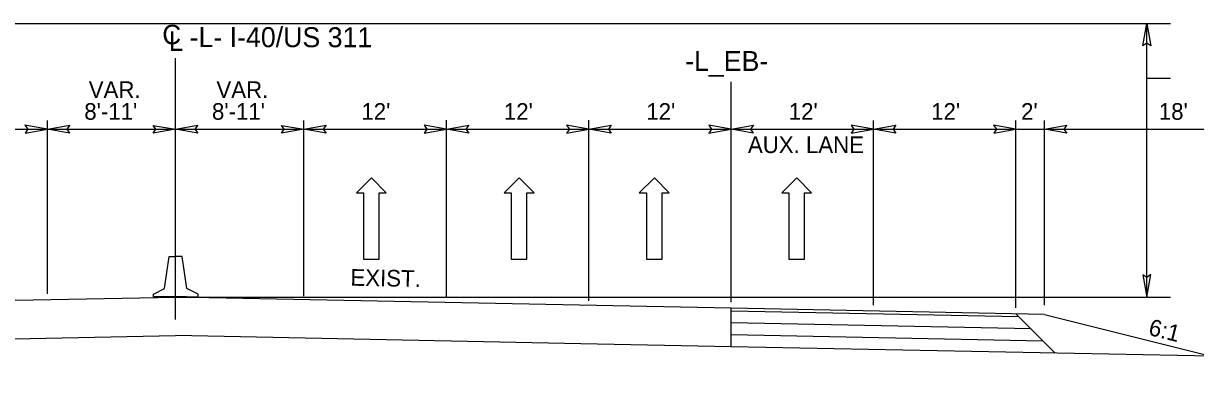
# Model space of a CAD drawing. Extents: x 1726582 to 1728895, y 538986 to 541550.
# Drawn here: x 1727397 to 1727891.1, y 541295.4 to 541445 of the extents above; entities that cross this region are included whole.
import ezdxf

# ---------------------------------------------------------------- set-up
doc = ezdxf.new("R2010")
doc.units = 0
for name, color, linetype in [('Default', 7, 'Continuous'), ('GSProposed', 7, 'Continuous'), ('GSRelocate', 7, 'Continuous'), ('GSRemove', 7, 'Continuous'), ('GSReplace', 7, 'Continuous')]:
    doc.layers.add(name, color=color, linetype=linetype)

msp = doc.modelspace()

# ---------------------------------------------------------------- linework, layer by layer
at = {"layer": 'Default'}
for p, q in [((1727250.93, 541445), (1727880.5, 541445)), ((1727870.5, 541329.79), (1727870.5, 541445)), ((1727695.28, 541327.57), (1727695.28, 541420.48)), ((1727870.5, 541422.01), (1727880.5, 541422.01)), ((1727407.04, 541331.18), (1727407.04, 541404.16)), ((1727515.13, 541330.19), (1727515.13, 541404.16)), ((1727575.29, 541329.97), (1727575.29, 541404.31)), ((1727635.34, 541328.19), (1727635.34, 541404.28)), ((1727695.28, 541327.57), (1727695.28, 541404.28)), ((1727755.32, 541326.37), (1727755.32, 541404.16)), ((1727815.37, 541326.37), (1727815.37, 541404.16)), ((1727815.37, 541325.17), (1727815.37, 541404.16)), ((1727827.38, 541326.37), (1727827.38, 541404.16)), ((1727346.99, 541400.46), (1727407.04, 541400.46)), ((1727407.04, 541400.46), (1727461.04, 541400.46)), ((1727461.04, 541400.46), (1727515.24, 541400.46)), ((1727515.24, 541400.46), (1727575.29, 541400.46)), ((1727575.29, 541400.46), (1727635.34, 541400.46)), ((1727635.34, 541400.46), (1727695.38, 541400.46)), ((1727695.38, 541400.46), (1727755.43, 541400.46)), ((1727755.43, 541400.46), (1727815.48, 541400.46)), ((1727755.43, 541400.46), (1727815.48, 541400.46)), ((1727815.48, 541400.46), (1727827.38, 541400.46)), ((1727827.38, 541400.46), (1727935.46, 541400.46)), ((1727543.74, 541379.98), (1727537.34, 541373.68)), ((1727549.94, 541373.68), (1727543.74, 541379.98)), ((1727606, 541379.98), (1727599.6, 541373.68)), ((1727612.2, 541373.68), (1727606, 541379.98)), ((1727663, 541379.98), (1727656.6, 541373.68)), ((1727669.2, 541373.68), (1727663, 541379.98)), ((1727723.05, 541379.98), (1727716.65, 541373.68)), ((1727729.25, 541373.68), (1727723.05, 541379.98)), ((1727537.34, 541373.68), (1727540.34, 541373.68)), ((1727540.34, 541373.68), (1727540.34, 541345.68)), ((1727546.94, 541345.68), (1727546.94, 541373.68)), ((1727546.94, 541373.68), (1727549.94, 541373.68)), ((1727599.6, 541373.68), (1727602.6, 541373.68)), ((1727602.6, 541373.68), (1727602.6, 541345.68)), ((1727609.2, 541345.68), (1727609.2, 541373.68)), ((1727609.2, 541373.68), (1727612.2, 541373.68)), ((1727656.6, 541373.68), (1727659.6, 541373.68)), ((1727659.6, 541373.68), (1727659.6, 541345.68)), ((1727666.2, 541345.68), (1727666.2, 541373.68)), ((1727666.2, 541373.68), (1727669.2, 541373.68)), ((1727716.65, 541373.68), (1727719.65, 541373.68)), ((1727719.65, 541373.68), (1727719.65, 541345.68)), ((1727726.25, 541345.68), (1727726.25, 541373.68)), ((1727726.25, 541373.68), (1727729.25, 541373.68)), ((1727540.34, 541345.68), (1727546.94, 541345.68)), ((1727602.6, 541345.68), (1727609.2, 541345.68)), ((1727659.6, 541345.68), (1727666.2, 541345.68)), ((1727719.65, 541345.68), (1727726.25, 541345.68)), ((1727461.04, 541329.79), (1727880.5, 541329.79))]:
    msp.add_line(p, q, dxfattribs=at)
for points in [[(1727868.89, 541435.66), (1727870.5, 541445.04), (1727872.17, 541435.61), (1727870.5, 541436.8)], [(1727397.66, 541398.85), (1727407.04, 541400.46), (1727397.61, 541402.13), (1727398.8, 541400.46)], [(1727416.42, 541398.85), (1727407.04, 541400.46), (1727416.47, 541402.13), (1727415.27, 541400.46)], [(1727451.66, 541402.08), (1727461.04, 541400.46), (1727451.61, 541398.8), (1727452.8, 541400.46)], [(1727470.41, 541398.85), (1727461.04, 541400.46), (1727470.47, 541402.13), (1727469.27, 541400.46)], [(1727505.76, 541402.08), (1727515.13, 541400.46), (1727505.7, 541398.79), (1727506.9, 541400.46)], [(1727524.51, 541398.85), (1727515.13, 541400.46), (1727524.56, 541402.13), (1727523.37, 541400.46)], [(1727565.91, 541398.85), (1727575.29, 541400.46), (1727565.86, 541402.13), (1727567.06, 541400.46)], [(1727584.67, 541398.85), (1727575.29, 541400.46), (1727584.72, 541402.13), (1727583.52, 541400.46)], [(1727625.96, 541398.85), (1727635.34, 541400.46), (1727625.91, 541402.13), (1727627.11, 541400.46)], [(1727644.72, 541398.85), (1727635.34, 541400.46), (1727644.77, 541402.13), (1727643.57, 541400.46)], [(1727685.9, 541398.85), (1727695.28, 541400.46), (1727685.85, 541402.13), (1727687.04, 541400.46)], [(1727704.65, 541398.85), (1727695.28, 541400.46), (1727704.71, 541402.13), (1727703.51, 541400.46)], [(1727745.94, 541398.85), (1727755.32, 541400.46), (1727745.89, 541402.13), (1727747.09, 541400.46)], [(1727764.7, 541398.85), (1727755.32, 541400.46), (1727764.75, 541402.13), (1727763.56, 541400.46)], [(1727805.99, 541398.85), (1727815.37, 541400.46), (1727805.94, 541402.13), (1727807.14, 541400.46)], [(1727836.76, 541398.85), (1727827.38, 541400.46), (1727836.81, 541402.13), (1727835.61, 541400.46)], [(1727868.88, 541339.17), (1727870.5, 541329.79), (1727872.17, 541339.22), (1727870.5, 541338.02)]]:
    msp.add_lwpolyline(points, close=True, dxfattribs=at)
at = {"layer": 'GSRemove'}
msp.add_line((1727461.04, 541320.33), (1727461.04, 541430.42), dxfattribs=at)
at = {"layer": 'GSReplace'}
for p, q in [((1727456.45, 541333.39), (1727458.42, 541346.9)), ((1727458.42, 541346.9), (1727461.14, 541346.9)), ((1727463.86, 541346.9), (1727461.14, 541346.9)), ((1727465.83, 541333.39), (1727463.86, 541346.9)), ((1727226.79, 541325.1), (1727461.04, 541329.79)), ((1727695.28, 541325.1), (1727461.04, 541329.79)), ((1727695.28, 541308.86), (1727695.28, 541325.1)), ((1727827.38, 541322.46), (1727695.28, 541325.1)), ((1727816.63, 541321.44), (1727695.28, 541323.87)), ((1727821.73, 541316.34), (1727695.28, 541318.87)), ((1727815.37, 541322.7), (1727831.94, 541306.13)), ((1727827.39, 541322.46), (1727935.46, 541295.44)), ((1727631.98, 541310.13), (1727461.04, 541313.55)), ((1727826.84, 541311.24), (1727695.28, 541313.87)), ((1727226.79, 541308.85), (1727461.04, 541313.53)), ((1727695.28, 541308.86), (1727631.98, 541310.13)), ((1727898, 541304.81), (1727695.28, 541308.86))]:
    msp.add_line(p, q, dxfattribs=at)
for points in [[(1727465.68, 541329.87), (1727451.73, 541329.87), (1727451.73, 541330.95), (1727456.45, 541333.39)], [(1727456.59, 541329.87), (1727470.55, 541329.87), (1727470.55, 541330.95), (1727465.83, 541333.39)]]:
    msp.add_lwpolyline(points, dxfattribs=at)

# ---------------------------------------------------------------- texts
at = {"layer": 'GSProposed'}
for s, p in [('VAR.', (1727424.49, 541413.65)), ('VAR.', (1727478.32, 541413.65)), ("8'-11'", (1727422.61, 541404.47)), ("8'-11'", (1727476.44, 541404.46)), ("12'", (1727539.45, 541404.46)), ("12'", (1727599.5, 541404.46)), ("12'", (1727659.55, 541404.46)), ("12'", (1727719.6, 541404.46)), ("12'", (1727779.64, 541404.46)), ("2'", (1727817.55, 541404.46)), ('AUX. LANE', (1727702.38, 541390.45))]:
    msp.add_text(s, height=7.005, dxfattribs=at).set_placement(p)
msp.add_text('EXIST.', height=7.005, rotation=358.8543, dxfattribs=at).set_placement((1727534.75, 541334.57))
at = {"layer": 'GSRelocate'}
msp.add_text("18'", height=7.005, dxfattribs=at).set_placement((1727875.61, 541404.46))
msp.add_text('6:1', height=7.005, rotation=345.9638, dxfattribs=at).set_placement((1727870.86, 541313.91))
at = {"layer": 'GSRemove'}
for s, height, rotation, p in [('C', 8.2, 0.0443, (1727455.51, 541436.27)), ('-L- I-40/US 311', 8.4214, 359.9417, (1727467.01, 541435.08)), ('L', 8.21, 359.9912, (1727458.24, 541433.48))]:
    msp.add_text(s, height=height, rotation=rotation, dxfattribs=at).set_placement(p)
msp.add_text('-L_EB-', height=8.421, dxfattribs=at).set_placement((1727675.91, 541425.02))

doc.saveas('drawing.dxf')
